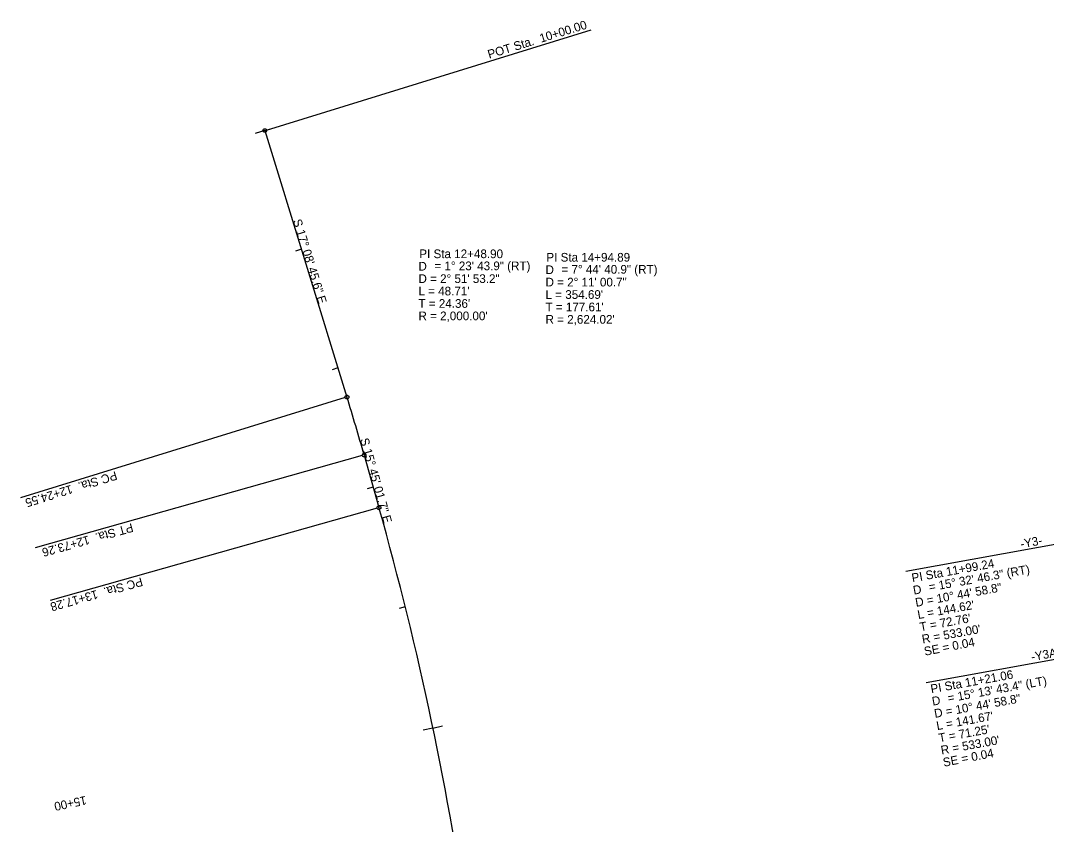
# Model space of a CAD drawing. Extents: x 1616561 to 1622460, y 896726 to 899651.
# Drawn here: x 1619648 to 1620474, y 898458 to 899105 of the extents above; entities that cross this region are included whole.
import ezdxf

# ---------------------------------------------------------------- set-up
doc = ezdxf.new("R2010")
doc.units = 0
for name, color, linetype in [('Prop Dimension', 7, 'Continuous'), ('Prop Superelevation  Arrow CELL', 7, 'Continuous'), ('Prop Superelevation Label', 7, 'Continuous'), ('Scratch_Level_1', 7, 'Continuous'), ('Sheet Cutting Line CELL', 7, 'Continuous'), ('Sheet North Arrow CELL', 7, 'Continuous'), ('Sheet Sticker Incomplete CELL', 7, 'Continuous')]:
    doc.layers.add(name, color=color, linetype=linetype)

msp = doc.modelspace()

# ---------------------------------------------------------------- linework, layer by layer
at = {"layer": 'Prop Superelevation  Arrow CELL'}
for p, q in [((1619874.15, 898920.8), (1619869.37, 898919.33)), ((1619903.63, 898825.25), (1619898.85, 898823.77)), ((1619931.92, 898729.33), (1619927.11, 898727.98)), ((1619957.81, 898632.75), (1619952.95, 898631.54))]:
    msp.add_line(p, q, dxfattribs=at)
at = {"layer": 'Prop Superelevation Label'}
for p, q in [((1619844.67, 899016.36), (1619837.03, 899014)), ((1619844.67, 899016.36), (1619852.31, 899018.71)), ((1619980.05, 898535.26), (1619972.22, 898533.63)), ((1619980.05, 898535.26), (1619987.88, 898536.89))]:
    msp.add_line(p, q, dxfattribs=at)
at = {"layer": 'Sheet Cutting Line CELL'}
for p, q in [((1619844.67, 899016.36), (1619910.87, 898801.79)), ((1619924.66, 898755.07), (1619936.61, 898712.71))]:
    msp.add_line(p, q, dxfattribs=at)
for centre, radius, start, end in [((1617999.75, 898212.18), 2000, 15.75048, 17.146), ((1617411.12, 898000.42), 2624.02, 8.00579, 15.75048)]:
    msp.add_arc(centre, radius, start, end, dxfattribs=at)
at = {"layer": 'Sheet North Arrow CELL'}
for p, q in [((1619846.1, 899016.8), (1620107.45, 899097.43)), ((1619909.43, 898801.35), (1619648.09, 898720.72)), ((1619923.22, 898754.67), (1619659.99, 898680.42)), ((1619935.17, 898712.3), (1619671.93, 898638.06))]:
    msp.add_line(p, q, dxfattribs=at)
for centre in [(1619844.67, 899016.36), (1619910.87, 898801.79), (1619924.66, 898755.07), (1619936.61, 898712.71)]:
    msp.add_circle(centre, 1.5, dxfattribs=at)
at = {"layer": 'Sheet Sticker Incomplete CELL'}
for p, q in [((1620360.73, 898661.56), (1620569.47, 898699.35)), ((1620376.97, 898571.85), (1620578.49, 898608.33))]:
    msp.add_line(p, q, dxfattribs=at)

# ---------------------------------------------------------------- texts
at = {"layer": 'Prop Dimension'}
msp.add_text('15+00', height=7, rotation=191.76068, dxfattribs=at).set_placement((1619700.43, 898480.62))
at = {"layer": 'Scratch_Level_1'}
for s, rotation, p in [('S 17%%d 08\' 45.6" E', 287.146, (1619867.24, 898943.88)), ('S 15%%d 45\' 01.7" E', 285.75048, (1619921.31, 898767.67))]:
    msp.add_text(s, height=7, rotation=rotation, dxfattribs=at).set_placement(p)
at = {"layer": 'Sheet North Arrow CELL'}
for s, rotation, p in [('POT Sta.  10+00.00', 17.146, (1620025.34, 899074.19)), ('PC Sta.  12+24.55', 197.146, (1619724.56, 898742.22)), ('PT Sta.  12+73.26', 195.75048, (1619737.65, 898700.25)), ('PC Sta.  13+17.28', 195.75048, (1619745.3, 898656.67))]:
    msp.add_text(s, height=7, rotation=rotation, dxfattribs=at).set_placement(p)
at = {"layer": 'Sheet Sticker Incomplete CELL'}
for s, p in [('PI Sta 12+48.90', (1619969.08, 898913.64)), ('PI Sta 14+94.89', (1620071.37, 898910.85)), ('D', (1619968.4, 898903.64)), ('= 1%%d 23\' 43.9" (RT)', (1619981.25, 898903.93)), ('D', (1620070.69, 898900.85)), ('= 7%%d 44\' 40.9" (RT)', (1620083.54, 898901.15)), ('D = 2%%d 51\' 53.2"', (1619968.4, 898893.64)), ('D = 2%%d 11\' 00.7"', (1620070.69, 898890.85)), ("L = 48.71'", (1619968.4, 898883.64)), ("L = 354.69'", (1620070.69, 898880.85)), ("T = 24.36'", (1619968.4, 898873.64)), ("R = 2,000.00'", (1619968.4, 898863.64)), ("T = 177.61'", (1620070.69, 898870.85)), ("R = 2,624.02'", (1620070.69, 898860.85))]:
    msp.add_text(s, height=7, dxfattribs=at).set_placement(p)
for s, rotation, p in [('-Y3-', 10.25995, (1620453.53, 898679.97)), ('PI Sta 11+99.24', 10.25995, (1620366.04, 898652.6)), ('= 15%%d 32\' 46.3" (RT)', 10.25995, (1620379.75, 898645.22)), ('D', 10.25995, (1620367.16, 898642.64)), ('D = 10%%d 44\' 58.8"', 10.25995, (1620368.94, 898632.8)), ("L = 144.62'", 10.25995, (1620370.72, 898622.96)), ("T = 72.76'", 10.25995, (1620372.5, 898613.12)), ("R = 533.00'", 10.25995, (1620374.28, 898603.28)), ('SE = 0.04', 11.03219, (1620376.07, 898593.44)), ('-Y3A-', 10.25995, (1620462.16, 898589.05)), ('PI Sta 11+21.06', 10.25995, (1620381.27, 898563.18)), ('= 15%%d 13\' 43.4" (LT)', 10.25995, (1620394.98, 898555.79)), ('D', 10.25995, (1620382.38, 898553.22)), ('D = 10%%d 44\' 58.8"', 10.25995, (1620384.17, 898543.37)), ("L = 141.67'", 10.25995, (1620385.95, 898533.53)), ("T = 71.25'", 10.25995, (1620387.73, 898523.69)), ("R = 533.00'", 10.25995, (1620389.51, 898513.85)), ('SE = 0.04', 11.03219, (1620391.29, 898504.01))]:
    msp.add_text(s, height=7, rotation=rotation, dxfattribs=at).set_placement(p)

doc.saveas('drawing.dxf')
